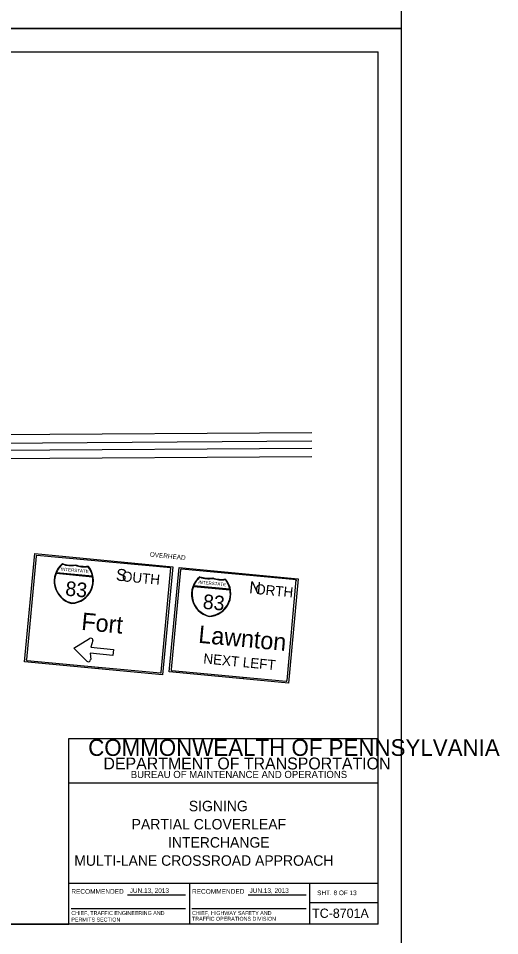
# Model space of a CAD drawing. Extents: x 644898 to 648326, y 298294 to 300670.
# Drawn here: x 648015 to 648326, y 299490 to 300083 of the extents above; entities that cross this region are included whole.
import ezdxf

# ---------------------------------------------------------------- set-up
doc = ezdxf.new("R2010")
doc.units = 0
for name, color, linetype in [('1', 7, 'Continuous'), ('2', 7, 'Continuous'), ('XCS-GRID-MIN', 7, 'Continuous')]:
    doc.layers.add(name, color=color, linetype=linetype)

msp = doc.modelspace()

# ---------------------------------------------------------------- linework, layer by layer
at = {"layer": '1'}
for p, q in [((647461.32, 300061.49), (648247.32, 300061.49)), ((648247.32, 299497.49), (648247.32, 300061.49)), ((648047.32, 299497.49), (648047.32, 299617.49)), ((648047.32, 299617.49), (648247.32, 299617.49)), ((648247.32, 299588.49), (648047.32, 299588.49)), ((648047.32, 299523.87), (648247.32, 299523.87)), ((648125.32, 299523.87), (648125.32, 299497.49)), ((648203.2, 299497.49), (648203.2, 299523.87)), ((648085.26, 299516.44), (648122.88, 299516.44)), ((648163.26, 299516.44), (648200.88, 299516.44)), ((648203.2, 299511.49), (648247.32, 299511.49)), ((648049.01, 299507.54), (648122.88, 299507.54)), ((648127.01, 299507.54), (648200.88, 299507.54)), ((648247.32, 299497.49), (647461.32, 299497.49)), ((647461.32, 299497.49), (648047.32, 299497.49))]:
    msp.add_line(p, q, dxfattribs=at)
at = {"layer": '2'}
for p, q in [((647982.82, 299813.87), (648204.57, 299815.27)), ((648204.57, 299809.66), (647787.82, 299806.87)), ((647787.32, 299802.74), (648204.57, 299805.13)), ((648204.57, 299799.51), (647982.95, 299798.24)), ((648018.72, 299667.12), (648025.45, 299737.01)), ((648026.32, 299735.38), (648019.98, 299668.53)), ((648025.44, 299737), (648114.57, 299728.51)), ((648043.36, 299730.16), (648043.36, 299730.16)), ((648051.61, 299729.41), (648051.61, 299729.41)), ((648059.74, 299728.66), (648059.74, 299728.66)), ((648114.57, 299728.51), (648107.97, 299658.62)), ((648039.24, 299724.29), (648062.74, 299722.04)), ((648062.74, 299722.41), (648039.36, 299724.66)), ((648107.19, 299660.26), (648113.38, 299727.84)), ((648112.29, 299660.63), (648118.78, 299728.11)), ((648119.65, 299726.48), (648113.61, 299662.01)), ((648118.78, 299728.1), (648195.61, 299720.78)), ((648132.2, 299721.7), (648132.2, 299721.7)), ((648140.45, 299720.95), (648140.45, 299720.95)), ((648148.57, 299720.2), (648148.57, 299720.2)), ((648188.44, 299654.97), (648194.43, 299720.12)), ((648195.61, 299720.78), (648189.31, 299653.29)), ((648128.07, 299715.83), (648151.57, 299713.58)), ((648151.57, 299713.95), (648128.2, 299716.2)), ((648050.6, 299675.78), (648060.76, 299682.2)), ((648062.86, 299680.76), (648061.66, 299676.62)), ((648059.08, 299667.46), (648050.6, 299675.78)), ((648061.66, 299676.62), (648076.32, 299675.03)), ((648076.32, 299675.03), (648075.83, 299671.06)), ((648075.83, 299671.06), (648061.17, 299672.65)), ((648061.17, 299672.65), (648061.56, 299668.49)), ((648066.52, 299662.56), (648018.72, 299667.12)), ((648020.38, 299667.9), (648066.62, 299663.58)), ((648066.52, 299662.56), (648066.62, 299663.58)), ((648066.62, 299663.58), (648066.52, 299662.56)), ((648066.62, 299663.58), (648106.6, 299659.92)), ((648107.97, 299658.62), (648066.52, 299662.56)), ((648160.08, 299656.08), (648112.29, 299660.63)), ((648113.91, 299661.38), (648160.18, 299657.09)), ((648160.08, 299656.08), (648160.18, 299657.09)), ((648160.18, 299657.09), (648160.08, 299656.08)), ((648160.18, 299657.09), (648187.84, 299654.57)), ((648189.31, 299653.29), (648160.08, 299656.08))]:
    msp.add_line(p, q, dxfattribs=at)
for points in [[(648113.38, 299727.84), (648026.82, 299735.76)], [(648194.53, 299720.11), (648120.15, 299726.86)]]:
    msp.add_lwpolyline(points, dxfattribs=at)
for centre, radius, start, end in [((648026.76, 299735.31), 0.528, 84.28941, 175.60129), ((648052.69, 299719.16), 14.78, 129.56625, 256.43614), ((648052.69, 299719.16), 14.47, 130.25861, 157.7735), ((648048.99, 299746.55), 16.98, 250.31621, 278.81628), ((648048.99, 299746.55), 17.29, 250.90674, 278.55521), ((648048.53, 299719.56), 14.78, 272.69635, 39.56625), ((648057.32, 299745.76), 17.29, 250.57728, 278.22575), ((648057.32, 299745.76), 16.98, 250.31621, 278.81628), ((648048.53, 299719.56), 14.47, 11.359, 38.87388), ((648052.69, 299719.16), 14.47, 159.0531, 256.43614), ((648112.87, 299727.21), 0.528, 354.14399, 84.50768), ((648120.09, 299726.41), 0.528, 84.28941, 175.60129), ((648048.53, 299719.56), 14.47, 272.69635, 10.07939), ((648141.52, 299710.7), 14.78, 129.56625, 256.43614), ((648141.52, 299710.7), 14.47, 130.25861, 157.7735), ((648137.83, 299738.09), 16.98, 250.31621, 278.81628), ((648137.83, 299738.09), 17.29, 250.90674, 278.55521), ((648137.36, 299711.1), 14.78, 272.69635, 39.56625), ((648146.15, 299737.3), 17.29, 250.57728, 278.22575), ((648146.15, 299737.3), 16.98, 250.31621, 278.81628), ((648137.36, 299711.1), 14.47, 11.359, 38.87388), ((648141.52, 299710.7), 14.47, 159.0531, 256.43614), ((648137.36, 299711.1), 14.47, 272.69635, 10.07939), ((648061.51, 299681.04), 1.4, 342.11994, 126.02657), ((648060.09, 299668.47), 1.4, 223.73147, 4.39698)]:
    msp.add_arc(centre, radius, start, end, dxfattribs=at)
for centre, major_axis, ratio, start_param, end_param in [((648193.9, 299719.47), (0.642, 0), 0.836215, 6.180979, 7.758122), ((648020.46, 299668.47), (-0.558, 0), 0.963153, 6.180104, 7.77084), ((648106.67, 299660.32), (0.496, 0), 0.990562, 4.621729, 6.195178), ((648113.98, 299661.95), (0, 0.539), 0.826049, 1.467715, 3.058451), ((648187.91, 299655.04), (0, -0.561), 0.892019, 6.192525, 7.765974)]:
    msp.add_ellipse(centre, major_axis=major_axis, ratio=ratio, start_param=start_param, end_param=end_param, dxfattribs=at)
at = {"layer": 'XCS-GRID-MIN'}
for points in [[(647421.32, 300670.49), (648262.32, 300670.49), (648262.32, 300076.49), (647421.32, 300076.49)], [(647421.32, 300076.49), (648262.32, 300076.49), (648262.32, 299482.49), (647421.32, 299482.49)]]:
    msp.add_lwpolyline(points, close=True, dxfattribs=at)

# ---------------------------------------------------------------- texts
at = {"layer": '1'}
for s, height, p in [('COMMONWEALTH OF PENNSYLVANIA', 10.7828, (648059.92, 299606.23)), ('DEPARTMENT OF TRANSPORTATION', 7.6837, (648069.78, 299597.48)), ('BUREAU OF MAINTENANCE AND OPERATIONS', 4.6253, (648087.42, 299591.91)), ('SIGNING', 6.75, (648124.97, 299570.43)), ('PARTIAL CLOVERLEAF', 6.75, (648088.01, 299558.68)), ('INTERCHANGE', 6.75, (648111.5, 299546.93)), ('MULTI-LANE CROSSROAD APPROACH', 6.75, (648050.91, 299535.18)), ('RECOMMENDED', 3.048, (648049.01, 299517.07)), ('RECOMMENDED', 3.048, (648127.01, 299517.07)), ('SHT. 8 OF 13', 3, (648207.91, 299516.18)), ('CHIEF, TRAFFIC ENGINEERING AND', 2.5, (648049.01, 299503.38)), ('CHIEF, HIGHWAY SAFETY AND', 2.5, (648127.01, 299503.38)), ('TC-8701A', 6, (648204.69, 299501.49)), ('PERMITS SECTION', 2.5, (648049.01, 299499.13)), ('TRAFFIC OPERATIONS DIVISION', 2.5, (648127.01, 299499.68))]:
    msp.add_text(s, height=height, dxfattribs=at).set_placement(p)
at = {"layer": '2'}
for s, height, rotation, p in [('OVERHEAD', 3, 354.47062, (648099.63, 299735.07)), ('INTERSTATE', 2.089, 354.56676, (648042.24, 299726.04)), ('S', 7.75, 354.58165, (648077.61, 299719.66)), ('OUTH', 6.5, 354.56831, (648081.49, 299719.16)), ('83', 9.406, 354.56583, (648044.86, 299709.91)), ('INTERSTATE', 2.089, 354.56676, (648131.07, 299717.58)), ('N', 7.75, 354.58165, (648163.74, 299711.46)), ('ORTH', 6.5, 354.56831, (648167.63, 299710.96)), ('83', 9.406, 354.56583, (648133.7, 299701.45)), ('Fort', 11.25, 354.56833, (648055.17, 299687.75)), ('Lawnton', 11.25, 354.56833, (648130.81, 299679.41)), ('NEXT LEFT', 6.493, 354.56831, (648134.15, 299666.07))]:
    msp.add_text(s, height=height, rotation=rotation, dxfattribs=at).set_placement(p)
for p in [(648086.79, 299517.65), (648164.24, 299517.65)]:
    msp.add_text('JUN.13, 2013', height=3, dxfattribs=at).set_placement(p)

doc.saveas('drawing.dxf')
